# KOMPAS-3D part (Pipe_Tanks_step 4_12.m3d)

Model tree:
1. X Axis
2. Y Axis
3. Z Axis  (labels: Valve Dy 150; Pipe Dn 150; T-Bend Dn 150)
     Òîëùèíà ñòåíêè 1 = 1

Referenced files in C:\Documents and Settings\kashirsky\Мои документы\Camtasia Studio\Pipelines3D\Tanks\: Tanks_step 4.a3d
Referenced files in C:\Program Files\ASCON\KOMPAS-3D V10\Libs\Piping\LOAD\: Piping_C_Pipe_150_1000.m3d
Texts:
  Pipe Dn 150
  Steel ASTM A295
  Three Point Plane
  Plane at Angle
  Line and Point Plane
  Axis through Two Vertices
  Axis of Feature
  Axis of Conical Surface
  Axis through Edge
  Trim by Surface
  Trim by Sketch
  Feature with No History
  Intersection Axis of Two Planes
  Two Line Plane
  Line and Face Plane
  Bend by line
  Hole in sheet body
  Cut in sheet body
  Point in CM
  Linear Dimension from Line to Point
  Surface Finish Symbol
  Geometric Tolerance Symbol
  Leader #1
  Leader #2
  Leader #3
  Shape Deviations and Datum
  Node point number
  Mark of coordination axis
  Node point designation
  Mark/Reference designation with leader
  Mark/reference designation on line
  Mark/Reference designation without leader
  Valve Dy 150
  T-Bend Dn 150
  Plane of section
